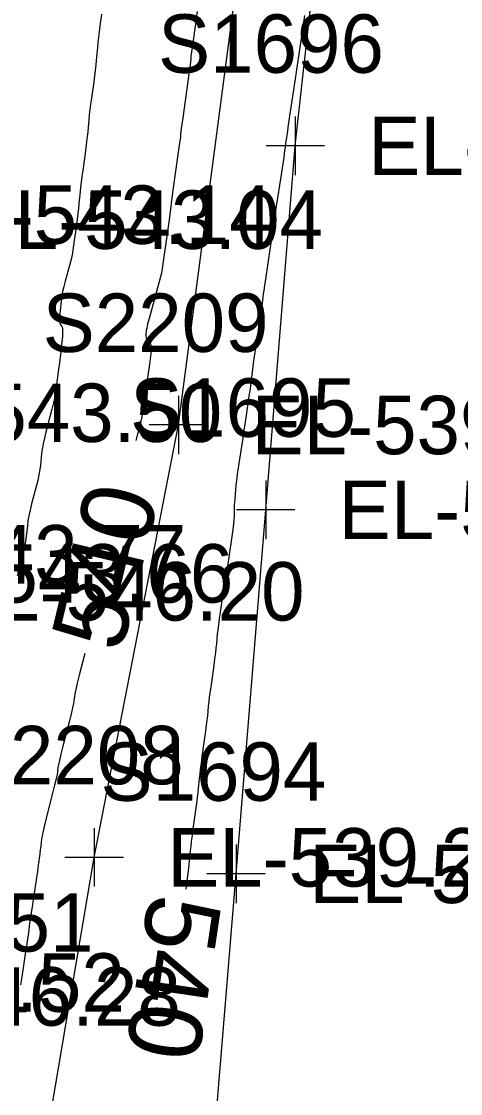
# Model space of a CAD drawing. Extents: x 1724534 to 1727318, y 657156 to 660047.
# Drawn here: x 1725540 to 1725570.1, y 659174.9 to 659248.3 of the extents above; entities that cross this region are included whole.
import ezdxf

# ---------------------------------------------------------------- set-up
doc = ezdxf.new("R2010")
doc.units = 0
for name, color, linetype in [('SURVEY - CONTOURS - Index with Text', 7, 'Continuous'), ('SURVEY - CONTOURS - Intermediate with optional Text', 7, 'Continuous'), ('SURVEY - DTM - Breaklines', 7, 'Continuous'), ('SURVEY - DTM - Breaklines - Points - Elevations', 7, 'Continuous'), ('SURVEY - DTM - Breaklines - Points - Locators', 7, 'Continuous'), ('SURVEY - DTM - Breaklines - Points - Numbers', 7, 'Continuous'), ('SURVEY - ROADSIDE BARRIERS - Points - Elevations', 7, 'Continuous'), ('SURVEY - TRANSPORTATION - Features', 7, 'Continuous'), ('SURVEY - TRANSPORTATION - Features - Points - Elevations', 7, 'Continuous'), ('SURVEY - TRANSPORTATION - Features - Points - Locators', 7, 'Continuous'), ('SURVEY - TRANSPORTATION - Features - Points - Numbers', 7, 'Continuous'), ('SURVEY - TRANSPORTATION - Roads - Points - Elevations', 7, 'Continuous')]:
    doc.layers.add(name, color=color, linetype=linetype)

msp = doc.modelspace()

# ---------------------------------------------------------------- linework, layer by layer
at = {"layer": 'SURVEY - CONTOURS - Index with Text'}
for points in [[(1725552.032, 659248.989), (1725551.704, 659246.672), (1725551.643, 659246.232), (1725551.604, 659245.931), (1725551.585, 659245.771), (1725551.564, 659245.532), (1725551.545, 659245.371), (1725551.506, 659245.07), (1725551.363, 659244.046), (1725551.034, 659241.722), (1725550.933, 659240.98), (1725550.915, 659240.822), (1725550.893, 659240.587), (1725550.875, 659240.429), (1725550.774, 659239.686), (1725550.362, 659236.771), (1725550.261, 659236.029), (1725550.243, 659235.872), (1725550.221, 659235.643), (1725550.203, 659235.485), (1725550.102, 659234.742), (1725549.585, 659231.091), (1725548.87, 659228.489), (1725548.734, 659227.988), (1725548.634, 659227.6), (1725548.57, 659227.325), (1725548.542, 659227.163), (1725548.514, 659226.882), (1725548.513, 659226.78), (1725548.529, 659226.684), (1725548.565, 659226.595), (1725548.618, 659226.511), (1725548.785, 659226.298), (1725548.839, 659226.217), (1725548.876, 659226.136), (1725548.894, 659226.054), (1725548.895, 659225.971), (1725548.874, 659225.749), (1725548.855, 659225.594), (1725548.754, 659224.851), (1725548.34, 659221.924), (1725548.241, 659221.244), (1725548.225, 659221.143), (1725547.828, 659219.633)], [(1725551.281, 659188.906), (1725551.37, 659189.674), (1725551.406, 659189.985), (1725551.43, 659190.179), (1725551.44, 659190.255), (1725551.449, 659190.301), (1725551.452, 659190.316), (1725551.454, 659190.326), (1725551.455, 659190.333), (1725551.456, 659190.335), (1725551.456, 659190.336), (1725551.459, 659190.369), (1725551.508, 659190.857), (1725551.577, 659191.551), (1725551.608, 659191.84), (1725551.649, 659192.183), (1725551.701, 659192.583), (1725551.763, 659193.038), (1725551.942, 659194.326), (1725552.003, 659194.781), (1725552.055, 659195.179), (1725552.096, 659195.522), (1725552.126, 659195.809), (1725552.194, 659196.499), (1725552.224, 659196.786), (1725552.265, 659197.129), (1725552.317, 659197.529), (1725552.38, 659197.985), (1725552.561, 659199.277), (1725552.624, 659199.733), (1725552.675, 659200.132), (1725552.716, 659200.474), (1725552.746, 659200.76), (1725552.811, 659201.445), (1725552.841, 659201.731), (1725552.882, 659202.074), (1725552.935, 659202.474), (1725552.998, 659202.931), (1725553.182, 659204.228), (1725553.245, 659204.685), (1725553.297, 659205.085), (1725553.338, 659205.426), (1725553.367, 659205.71), (1725553.43, 659206.389), (1725553.46, 659206.673), (1725553.501, 659207.016), (1725553.553, 659207.417), (1725553.618, 659207.876), (1725553.805, 659209.178), (1725553.869, 659209.613), (1725553.92, 659209.944), (1725553.959, 659210.168), (1725553.985, 659210.287), (1725554.037, 659210.464), (1725554.063, 659210.588), (1725554.103, 659210.827), (1725554.158, 659211.182), (1725554.226, 659211.652), (1725554.426, 659213.059), (1725554.491, 659213.54), (1725554.538, 659213.925), (1725554.566, 659214.216), (1725554.575, 659214.413), (1725554.575, 659214.81), (1725554.575, 659214.941), (1725554.575, 659215.034), (1725554.575, 659215.091), (1725554.575, 659215.11), (1725554.575, 659215.111), (1725554.578, 659215.142), (1725554.586, 659215.236), (1725554.599, 659215.392), (1725554.618, 659215.609), (1725554.674, 659216.273), (1725554.702, 659216.552), (1725554.743, 659216.893), (1725554.797, 659217.295), (1725554.864, 659217.759), (1725555.126, 659219.51), (1725555.173, 659219.822), (1725555.201, 659220.012), (1725555.21, 659220.08), (1725555.212, 659220.099), (1725555.223, 659220.174), (1725555.254, 659220.384), (1725555.305, 659220.729), (1725555.377, 659221.209), (1725555.595, 659222.668), (1725555.67, 659223.172), (1725555.729, 659223.587), (1725555.774, 659223.914), (1725555.804, 659224.153), (1725555.863, 659224.672), (1725555.893, 659224.915), (1725555.94, 659225.253), (1725556.003, 659225.686), (1725556.082, 659226.215), (1725556.315, 659227.754), (1725556.394, 659228.279), (1725556.456, 659228.701), (1725556.5, 659229.021), (1725556.528, 659229.237), (1725556.577, 659229.677), (1725556.605, 659229.898), (1725556.652, 659230.23), (1725556.718, 659230.674), (1725557.054, 659232.858), (1725557.138, 659233.409), (1725557.202, 659233.84), (1725557.247, 659234.151), (1725557.271, 659234.341), (1725557.31, 659234.689), (1725557.336, 659234.884), (1725557.383, 659235.21), (1725557.453, 659235.666), (1725557.544, 659236.252), (1725557.816, 659237.988), (1725557.906, 659238.569), (1725557.974, 659239.01), (1725558.018, 659239.31), (1725558.04, 659239.47), (1725558.067, 659239.709), (1725558.075, 659239.788), (1725558.082, 659239.844), (1725558.085, 659239.878), (1725558.087, 659239.889), (1725558.087, 659239.891), (1725558.1, 659239.976), (1725558.138, 659240.229), (1725558.202, 659240.652), (1725558.291, 659241.243), (1725558.563, 659243.044), (1725558.653, 659243.644), (1725558.719, 659244.091), (1725558.762, 659244.386), (1725558.781, 659244.528), (1725558.801, 659244.705), (1725558.821, 659244.851), (1725558.865, 659245.155), (1725558.935, 659245.618), (1725559.029, 659246.24), (1725559.314, 659248.111), (1725559.408, 659248.729)], [(1725544.34, 659205.054), (1725543.957, 659203.562), (1725543.816, 659203.005), (1725543.712, 659202.576), (1725543.646, 659202.275), (1725543.616, 659202.101), (1725543.586, 659201.807), (1725543.557, 659201.633), (1725543.491, 659201.333), (1725543.389, 659200.907), (1725543.25, 659200.353), (1725542.831, 659198.709), (1725542.692, 659198.155), (1725542.59, 659197.727), (1725542.523, 659197.424), (1725542.493, 659197.248), (1725542.461, 659196.944), (1725542.431, 659196.767), (1725542.365, 659196.466), (1725542.264, 659196.04), (1725542.127, 659195.489), (1725541.713, 659193.853), (1725541.576, 659193.302), (1725541.474, 659192.874), (1725541.408, 659192.571), (1725541.377, 659192.391), (1725541.342, 659192.078), (1725541.32, 659191.881), (1725541.311, 659191.809), (1725541.303, 659191.756), (1725541.278, 659191.588), (1725541.27, 659191.52), (1725541.26, 659191.434), (1725541.248, 659191.332), (1725541.216, 659191.037), (1725541.193, 659190.862), (1725541.149, 659190.555), (1725541.085, 659190.118), (1725540.999, 659189.551), (1725540.743, 659187.864), (1725540.657, 659187.297), (1725540.549, 659186.559), (1725540.527, 659186.388), (1725540.496, 659186.108), (1725540.474, 659185.936), (1725540.43, 659185.631), (1725540.365, 659185.193), (1725540.279, 659184.622), (1725540.02, 659182.92), (1725539.934, 659182.352)]]:
    msp.add_lwpolyline(points, dxfattribs=at)
at = {"layer": 'SURVEY - CONTOURS - Intermediate with optional Text'}
msp.add_lwpolyline([(1725545.519, 659249.093), (1725545.365, 659248.012), (1725545.311, 659247.616), (1725545.265, 659247.24), (1725545.225, 659246.883), (1725545.192, 659246.546), (1725545.115, 659245.674), (1725545.083, 659245.336), (1725545.042, 659244.974), (1725544.994, 659244.59), (1725544.939, 659244.183), (1725544.781, 659243.068), (1725544.725, 659242.662), (1725544.677, 659242.283), (1725544.637, 659241.929), (1725544.605, 659241.601), (1725544.529, 659240.761), (1725544.496, 659240.431), (1725544.455, 659240.073), (1725544.407, 659239.686), (1725544.35, 659239.27), (1725544.187, 659238.123), (1725544.13, 659237.709), (1725544.082, 659237.326), (1725544.041, 659236.975), (1725544.009, 659236.655), (1725543.934, 659235.844), (1725543.902, 659235.523), (1725543.861, 659235.167), (1725543.811, 659234.778), (1725543.753, 659234.354), (1725543.586, 659233.179), (1725543.532, 659232.793), (1725543.493, 659232.517), (1725543.461, 659232.296), (1725543.461, 659232.294), (1725543.448, 659232.247), (1725543.41, 659232.106), (1725543.345, 659231.872), (1725542.981, 659230.547), (1725542.887, 659230.18), (1725542.811, 659229.827), (1725542.752, 659229.49), (1725542.712, 659229.166), (1725542.628, 659228.324), (1725542.606, 659228.041), (1725542.602, 659227.823), (1725542.617, 659227.67), (1725542.651, 659227.583), (1725542.765, 659227.437), (1725542.799, 659227.353), (1725542.816, 659227.212), (1725542.814, 659227.012), (1725542.796, 659226.756), (1725542.722, 659225.994), (1725542.69, 659225.687), (1725542.649, 659225.336), (1725542.598, 659224.942), (1725542.538, 659224.505), (1725542.365, 659223.28), (1725542.307, 659222.877), (1725542.265, 659222.585), (1725542.227, 659222.333), (1725542.217, 659222.295), (1725542.199, 659222.227), (1725542.153, 659222.052), (1725542.079, 659221.77), (1725541.667, 659220.203), (1725541.562, 659219.78), (1725541.478, 659219.394), (1725541.415, 659219.045), (1725541.374, 659218.733), (1725541.294, 659217.951), (1725541.253, 659217.639), (1725541.19, 659217.289), (1725541.107, 659216.901), (1725541.001, 659216.475), (1725540.692, 659215.288), (1725540.586, 659214.862), (1725540.502, 659214.475), (1725540.439, 659214.127), (1725540.397, 659213.818), (1725540.314, 659213.045), (1725540.272, 659212.735), (1725540.209, 659212.386), (1725540.125, 659211.997), (1725540.02, 659211.569), (1725539.711, 659210.374)], dxfattribs=at)
at = {"layer": 'SURVEY - DTM - Breaklines'}
msp.add_lwpolyline([(1725525.942, 659009.271), (1725526.399, 659011.158), (1725528.918, 659041.105), (1725531.461, 659071.052), (1725534.8, 659101.37), (1725536.346, 659131.334), (1725539.898, 659161.171), (1725544.971, 659191.09), (1725550.75, 659220.691), (1725554.674, 659250.537), (1725558.308, 659280.317), (1725560.346, 659299.038), (1725563.922, 659328.825), (1725567.992, 659357.481)], dxfattribs=at)
at = {"layer": 'SURVEY - DTM - Breaklines - Points - Locators'}
for p, q in [((1725550.75, 659222.691), (1725550.75, 659218.691)), ((1725552.75, 659220.691), (1725548.75, 659220.691)), ((1725544.971, 659193.09), (1725544.971, 659189.09)), ((1725546.971, 659191.09), (1725542.971, 659191.09))]:
    msp.add_line(p, q, dxfattribs=at)
at = {"layer": 'SURVEY - TRANSPORTATION - Features'}
msp.add_lwpolyline([(1725552.257, 658864.379), (1725550.906, 658889.348), (1725550.236, 658914.341), (1725548.733, 658939.305), (1725548.535, 658964.315), (1725548.579, 658989.617), (1725548.091, 659014.622), (1725548.852, 659039.619), (1725549.567, 659064.874), (1725549.301, 659089.91), (1725550.369, 659114.889), (1725551.556, 659139.862), (1725552.642, 659165.042), (1725554.694, 659189.961), (1725556.721, 659214.883), (1725558.747, 659239.804), (1725561.49, 659264.678)], dxfattribs=at)
at = {"layer": 'SURVEY - TRANSPORTATION - Features - Points - Locators'}
for p, q in [((1725558.747, 659241.804), (1725558.747, 659237.804)), ((1725560.747, 659239.804), (1725556.747, 659239.804)), ((1725556.721, 659216.883), (1725556.721, 659212.883)), ((1725558.721, 659214.883), (1725554.721, 659214.883)), ((1725554.694, 659191.961), (1725554.694, 659187.961)), ((1725556.694, 659189.961), (1725552.694, 659189.961))]:
    msp.add_line(p, q, dxfattribs=at)

# ---------------------------------------------------------------- texts
at = {"layer": 'SURVEY - CONTOURS - Index with Text'}
for rotation, p in [(76.54576, (1725546.844, 659205.018)), (261.554, (1725548.765, 659188.723))]:
    msp.add_text('540', height=5, rotation=rotation, dxfattribs=at).set_placement(p)
at = {"layer": 'SURVEY - DTM - Breaklines - Points - Elevations'}
for s, p in [('EL-539.58', (1725555.75, 659218.691)), ('EL-539.26', (1725549.971, 659189.09))]:
    msp.add_text(s, height=4, dxfattribs=at).set_placement(p)
at = {"layer": 'SURVEY - DTM - Breaklines - Points - Numbers'}
for s, p in [('S2209', (1725541.447, 659225.691)), ('S2208', (1725535.636, 659196.09))]:
    msp.add_text(s, height=4, dxfattribs=at).set_placement(p)
at = {"layer": 'SURVEY - ROADSIDE BARRIERS - Points - Elevations'}
for s, p in [('EL-546.20', (1725534.697, 659207.302)), ('EL-546.28', (1725526.221, 659179.564))]:
    msp.add_text(s, height=4, dxfattribs=at).set_placement(p)
at = {"layer": 'SURVEY - TRANSPORTATION - Features - Points - Elevations'}
for s, p in [('EL-540.05', (1725563.747, 659237.804)), ('EL-543.04', (1725535.962, 659232.747)), ('EL-540.21', (1725561.721, 659212.883)), ('EL-543.66', (1725529.817, 659208.531)), ('EL-540.37', (1725559.694, 659187.961)), ('EL-544.52', (1725522.386, 659180.521))]:
    msp.add_text(s, height=4, dxfattribs=at).set_placement(p)
at = {"layer": 'SURVEY - TRANSPORTATION - Features - Points - Numbers'}
for s, p in [('S1696', (1725549.349, 659244.804)), ('S1695', (1725547.433, 659219.883)), ('S1694', (1725545.406, 659194.961))]:
    msp.add_text(s, height=4, dxfattribs=at).set_placement(p)
at = {"layer": 'SURVEY - TRANSPORTATION - Roads - Points - Elevations'}
for s, p in [('EL-543.14', (1725532.51, 659233.091)), ('EL-543.50', (1725529.059, 659219.528)), ('EL-543.77', (1725526.595, 659209.838)), ('EL-544.51', (1725520.243, 659184.636))]:
    msp.add_text(s, height=4, dxfattribs=at).set_placement(p)

doc.saveas('drawing.dxf')
